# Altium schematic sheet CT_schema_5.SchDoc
size 178 x 159 mm
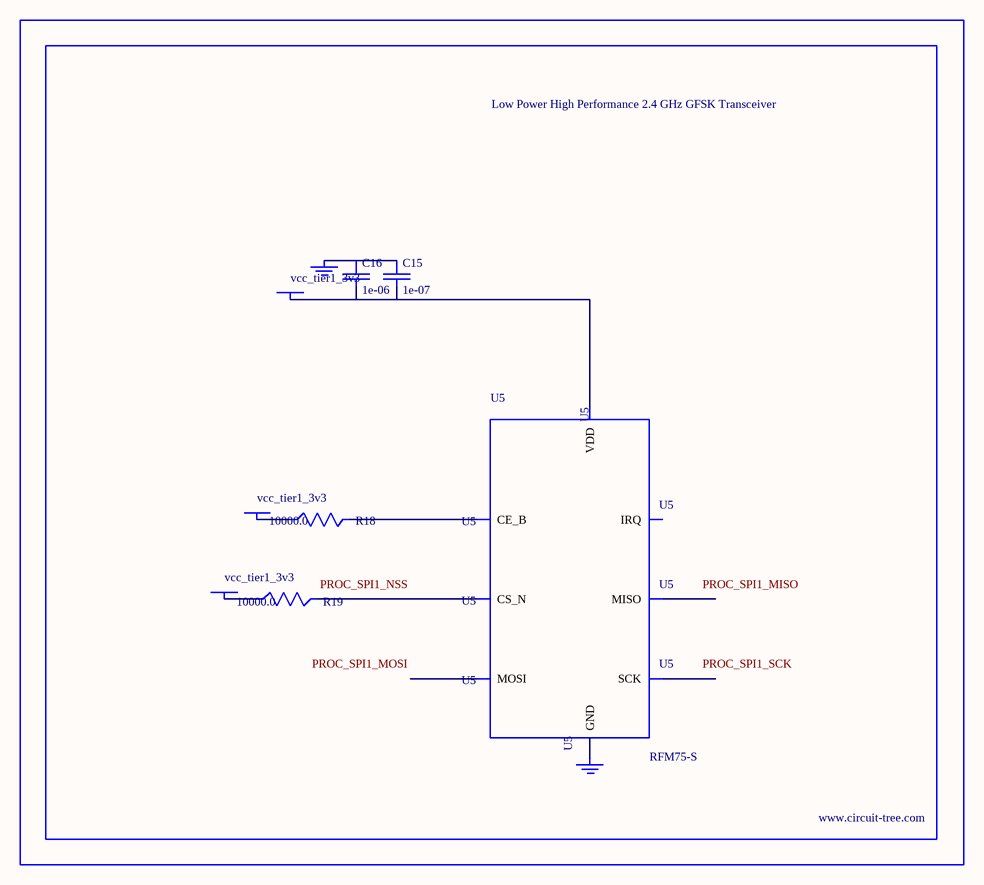
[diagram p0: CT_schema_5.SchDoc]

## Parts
BORDER4  (no value)
C15  1e-07  [C0402]
C16  1e-06  [C0603]
GND_INSTANCE_4_0  (no value)
GND_INSTANCE_4_1  (no value)
POWER_INSTANCE_4_0  vcc_tier1_3v3
POWER_INSTANCE_4_1  vcc_tier1_3v3
POWER_INSTANCE_4_2  vcc_tier1_3v3
R18  10000.0  [R0603]
R19  10000.0  [R0603]
U5  RFM75-S  [RFM75-S]

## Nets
NetC15_1: C15.1 C16.1 GND_INSTANCE_4_0.0(GND)
NetC15_2: C15.2 C16.2 POWER_INSTANCE_4_0.0(PWR) U5.2(VDD)
NetGND_INSTANCE_4_1_0: GND_INSTANCE_4_1.0(GND) U5.1(GND)
NetPOWER_INSTANCE_4_1_0: POWER_INSTANCE_4_1.0(PWR) R18.1
NetPOWER_INSTANCE_4_2_0: POWER_INSTANCE_4_2.0(PWR) R19.1
NetR18_2: R18.2 U5.3(CE_B)
NetR19_2: R19.2 U5.4(CS_N)

Not connected (* = marked no-connect by the designer): U5 5(SCK) 6(MOSI) 7(MISO) 8(IRQ)

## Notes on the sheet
- Labels drawn without touching a wire or pin: PROC_SPI1_MISO, PROC_SPI1_MOSI, PROC_SPI1_NSS, PROC_SPI1_SCK

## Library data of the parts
BORDER4 = BORDER_PAGE4
C15 = C0402C104K3RACTU
C16 = C0603C105K3RACTU
GND_INSTANCE_4_0 GND_INSTANCE_4_1 = GND
POWER_INSTANCE_4_0-POWER_INSTANCE_4_2 = PWR
R18 R19 = RC0603JR-0710KL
